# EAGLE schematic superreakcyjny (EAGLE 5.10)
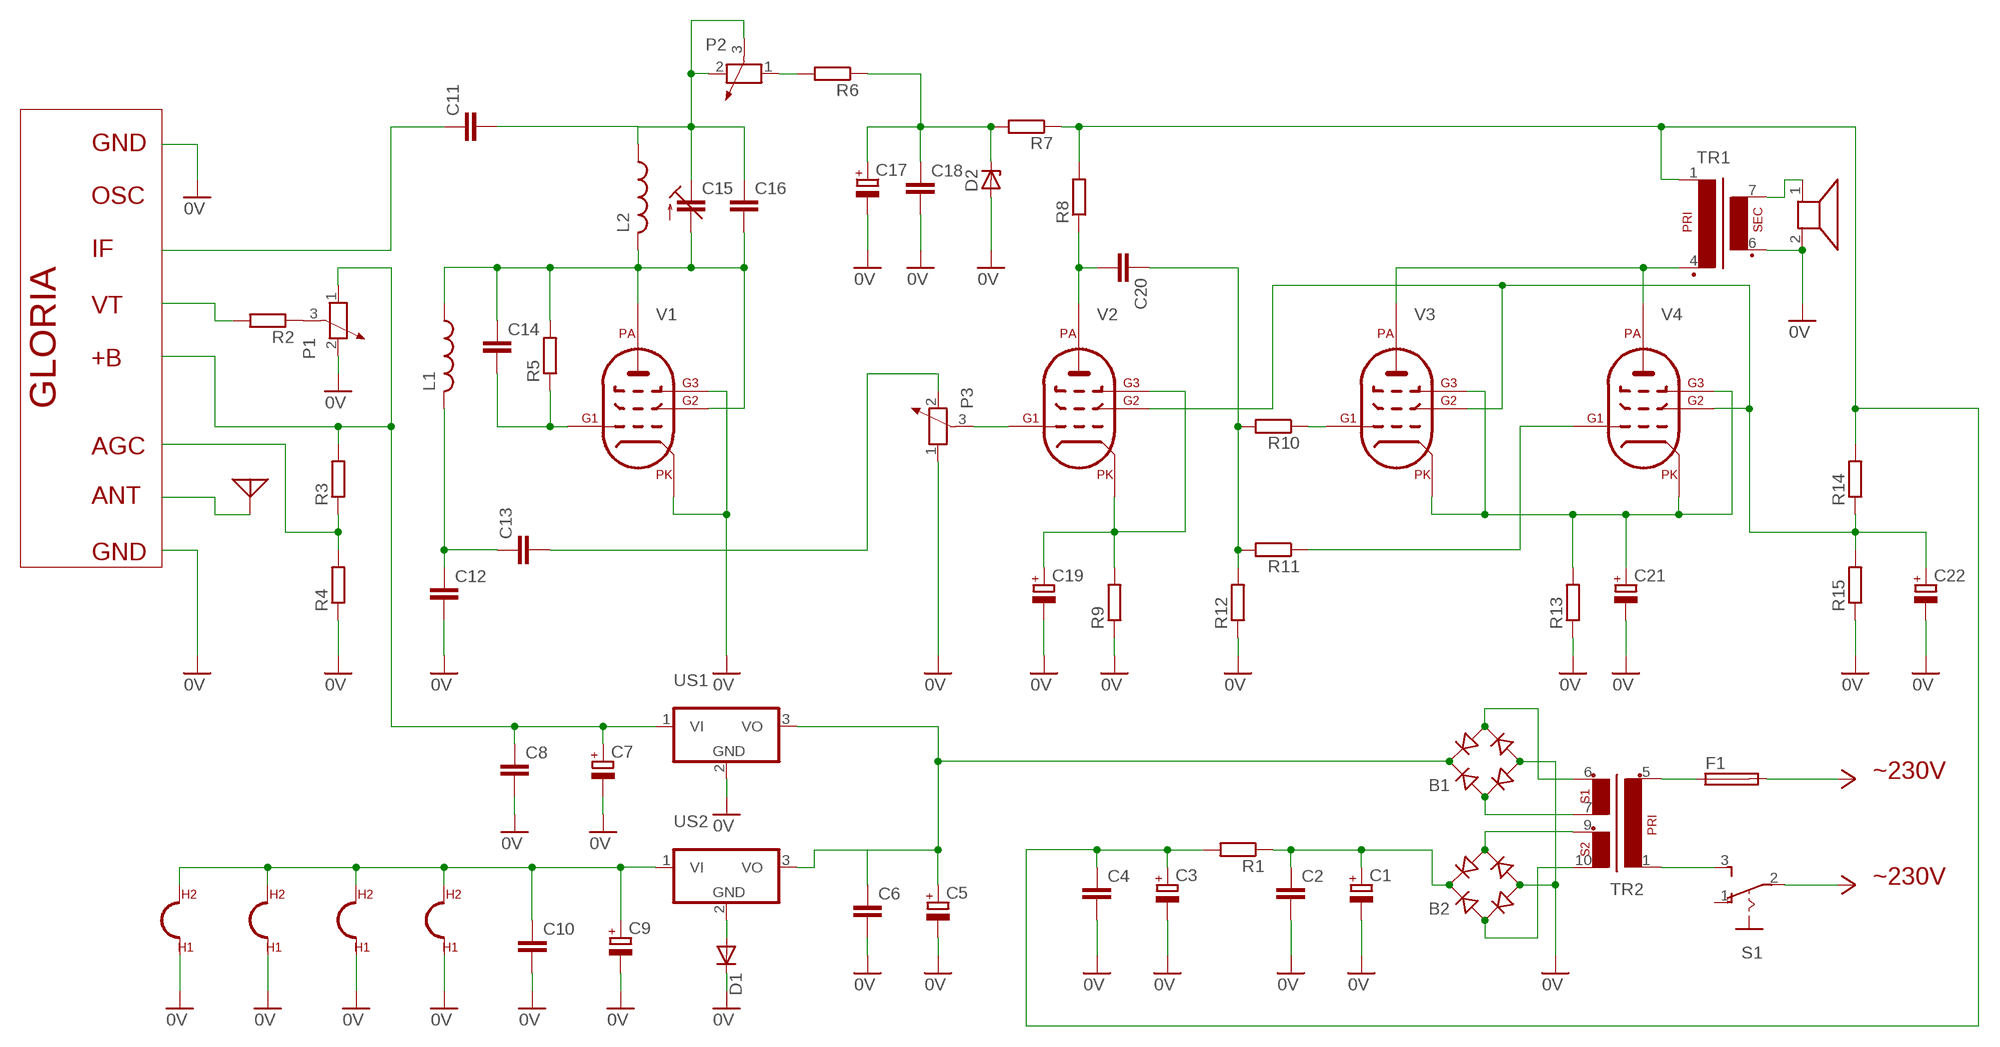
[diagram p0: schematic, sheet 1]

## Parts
ANT1  ANTENNA  [PAD-01]
B1  RB1A  [RB1A]
B2  RB1A  [RB1A]
C1  CPOL-EU139CLL-2W  [139CLL-2W]
C2  C-EU025-024X044  [C025-024X044]
C3  CPOL-EU139CLL-2W  [139CLL-2W]
C4  C-EU025-024X044  [C025-024X044]
C5  CPOL-EU139CLL-2W  [139CLL-2W]
C6  C-EU025-024X044  [C025-024X044]
C7  CPOL-EU139CLL-2W  [139CLL-2W]
C8  C-EU025-024X044  [C025-024X044]
C9  CPOL-EU139CLL-2W  [139CLL-2W]
C10  C-EU025-024X044  [C025-024X044]
C11  C-EU025-024X044  [C025-024X044]
C12  C-EU025-024X044  [C025-024X044]
C13  C-EU025-024X044  [C025-024X044]
C14  C-EU025-024X044  [C025-024X044]
C15  C-TRIMM808-1  [CTRIM808-1]
C16  C-EU025-024X044  [C025-024X044]
C17  CPOL-EU139CLL-2W  [139CLL-2W]
C18  C-EU025-024X044  [C025-024X044]
C19  CPOL-EU139CLL-2W  [139CLL-2W]
C20  C-EU025-024X044  [C025-024X044]
C21  CPOL-EU139CLL-2W  [139CLL-2W]
C22  CPOL-EU139CLL-2W  [139CLL-2W]
D1  1N4004  [DO41-10]
D2  1N821  [DO35Z10]
F1  19559  [19559]
L1  L-US0204/5  [0204/5]
L2  L-US0204/5  [0204/5]
P1  POTENTIOMETER_PT-10  [PT-10]
P2  POTENTIOMETER_PT-10  [PT-10]
P3  POTENTIOMETER_PT-10  [PT-10]
R1  R-EU_0204/2V  [0204V]
R2  R-EU_0204/2V  [0204V]
R3  R-EU_0204/2V  [0204V]
R4  R-EU_0204/2V  [0204V]
R5  R-EU_0204/2V  [0204V]
R6  R-EU_0204/2V  [0204V]
R7  R-EU_0204/2V  [0204V]
R8  R-EU_0204/2V  [0204V]
R9  R-EU_0204/2V  [0204V]
R10  R-EU_0204/2V  [0204V]
R11  R-EU_0204/2V  [0204V]
R12  R-EU_0204/2V  [0204V]
R13  R-EU_0204/2V  [0204V]
R14  R-EU_0204/2V  [0204V]
R15  R-EU_0204/2V  [0204V]
S1  255SB  [255SB]
SP1  AL30P  [AL30P]
TR1  EE20-1  [EE20-1]
TR2  EI38-2  [EI38-2]
US1  786TV  [TO220V]
US2  786TV  [TO220V]

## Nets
0V: B1.- B2.- C1.- C2.2 C3.- C4.2 C5.- C6.2 C7.- C8.2 C9.- C10.2 C12.2 C17.- C18.2 C19.- C21.- C22.- D1.C D2.A P1.2 P3.1 R4.1 R9.1 R12.1 R13.1 R15.1 SP1.2 TR1.6(S3)
+3V3: F1.2 S1.2(P)
N$1: C21.+ R13.2
N$2: R10.1
N$3: R11.1
N$4: C20.1 R10.2 R11.2 R12.2
N$5: TR1.4(P2)
N$6: SP1.1 TR1.7(S4)
N$7: C19.+ R9.2
N$8: C22.+ R14.1 R15.2
N$9: C17.+ C18.1 D2.C R6.1 R7.2
N$10: D1.A US2.2(GND)
N$11: C11.1
N$12: C20.2 R8.1
N$13: P3.3
N$14: R3.1 R4.2
N$15: C14.2 R5.1
N$16: C12.1 C13.1 L1.2
N$17: C13.2 P3.2
N$18: C11.2 C15.1(E) C16.1 L2.1 P2.2 P2.3
N$19: P2.1 R6.2
N$20: C14.1 C15.2(A) C16.2 L1.1 L2.2 R5.2
N$21: C7.+ C8.1 P1.1 R3.2 US1.1(VI)
N$22: ANT1.1
N$23: R2.2
N$24: P1.3 R2.1
N$25: B1.AC2 TR2.6
N$26: B1.AC1 TR2.7
N$27: B2.AC2 TR2.9
N$28: B2.AC1 TR2.10
N$29: S1.3(S) TR2.1
N$30: B2.+ C1.+ C2.1 R1.1
N$31: C3.+ C4.1 R1.2 R7.1 R8.2 R14.2 TR1.1
N$32: B1.+ C5.+ C6.1 US1.3(VO) US2.3(VO)
N$33: F1.1 TR2.5
N$34: C9.+ C10.1 US2.1(VI)
Unconnected: S1.1(O) US1.2(GND)

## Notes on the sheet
- GND
- OSC
- IF
- VT
- +B
- GLORIA
- AGC
- ANT
- GND
- ~230V
- ~230V

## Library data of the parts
ANT1 = discrete:ANTENNA: Antenna
B1 B2 = rectifier:RB1A: RECTIFIER 1 A
C1 C3 C5 C7 C9 C17 C19 C21 C22 = rcl:CPOL-EU: POLARIZED CAPACITOR, European symbol
C2 C4 C6 C8 C10-C14 C16 C18 C20 = rcl:C-EU: CAPACITOR, European symbol
C15 = rcl:C-TRIMM: Trimm capacitor
D1 = diode:1N4004: DIODE
D2 = diode:1N821: Reference DIODE
F1 = fuse:19559: FUSE HOLDER
L1 L2 = rcl:L-US: INDUCTOR, American symbol
P1-P3 = rcl:POTENTIOMETER_: Potentiometer
R1-R15 = rcl:R-EU_: RESISTOR, European symbol
S1 = switch:255SB: SLIDING SWITCH Distributor Buerklin, 11G810
SP1 = buzzer:AL30P: SPEAKER
TR1 = trafo:EE20-1: TRANSFORMER 1 primary winding, 1 secondary winding ERA
TR2 = trafo:EI38-2: TRANSFORMER 1 primary winding, 2 secondary windings ERA
US1 US2 = linear:78*: Positive VOLTAGE REGULATOR Source: http://cache.national.com/ds/LM/LM78L05.pdf http://www.fairchildsemi.com/ds/LM/LM7805.pdf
